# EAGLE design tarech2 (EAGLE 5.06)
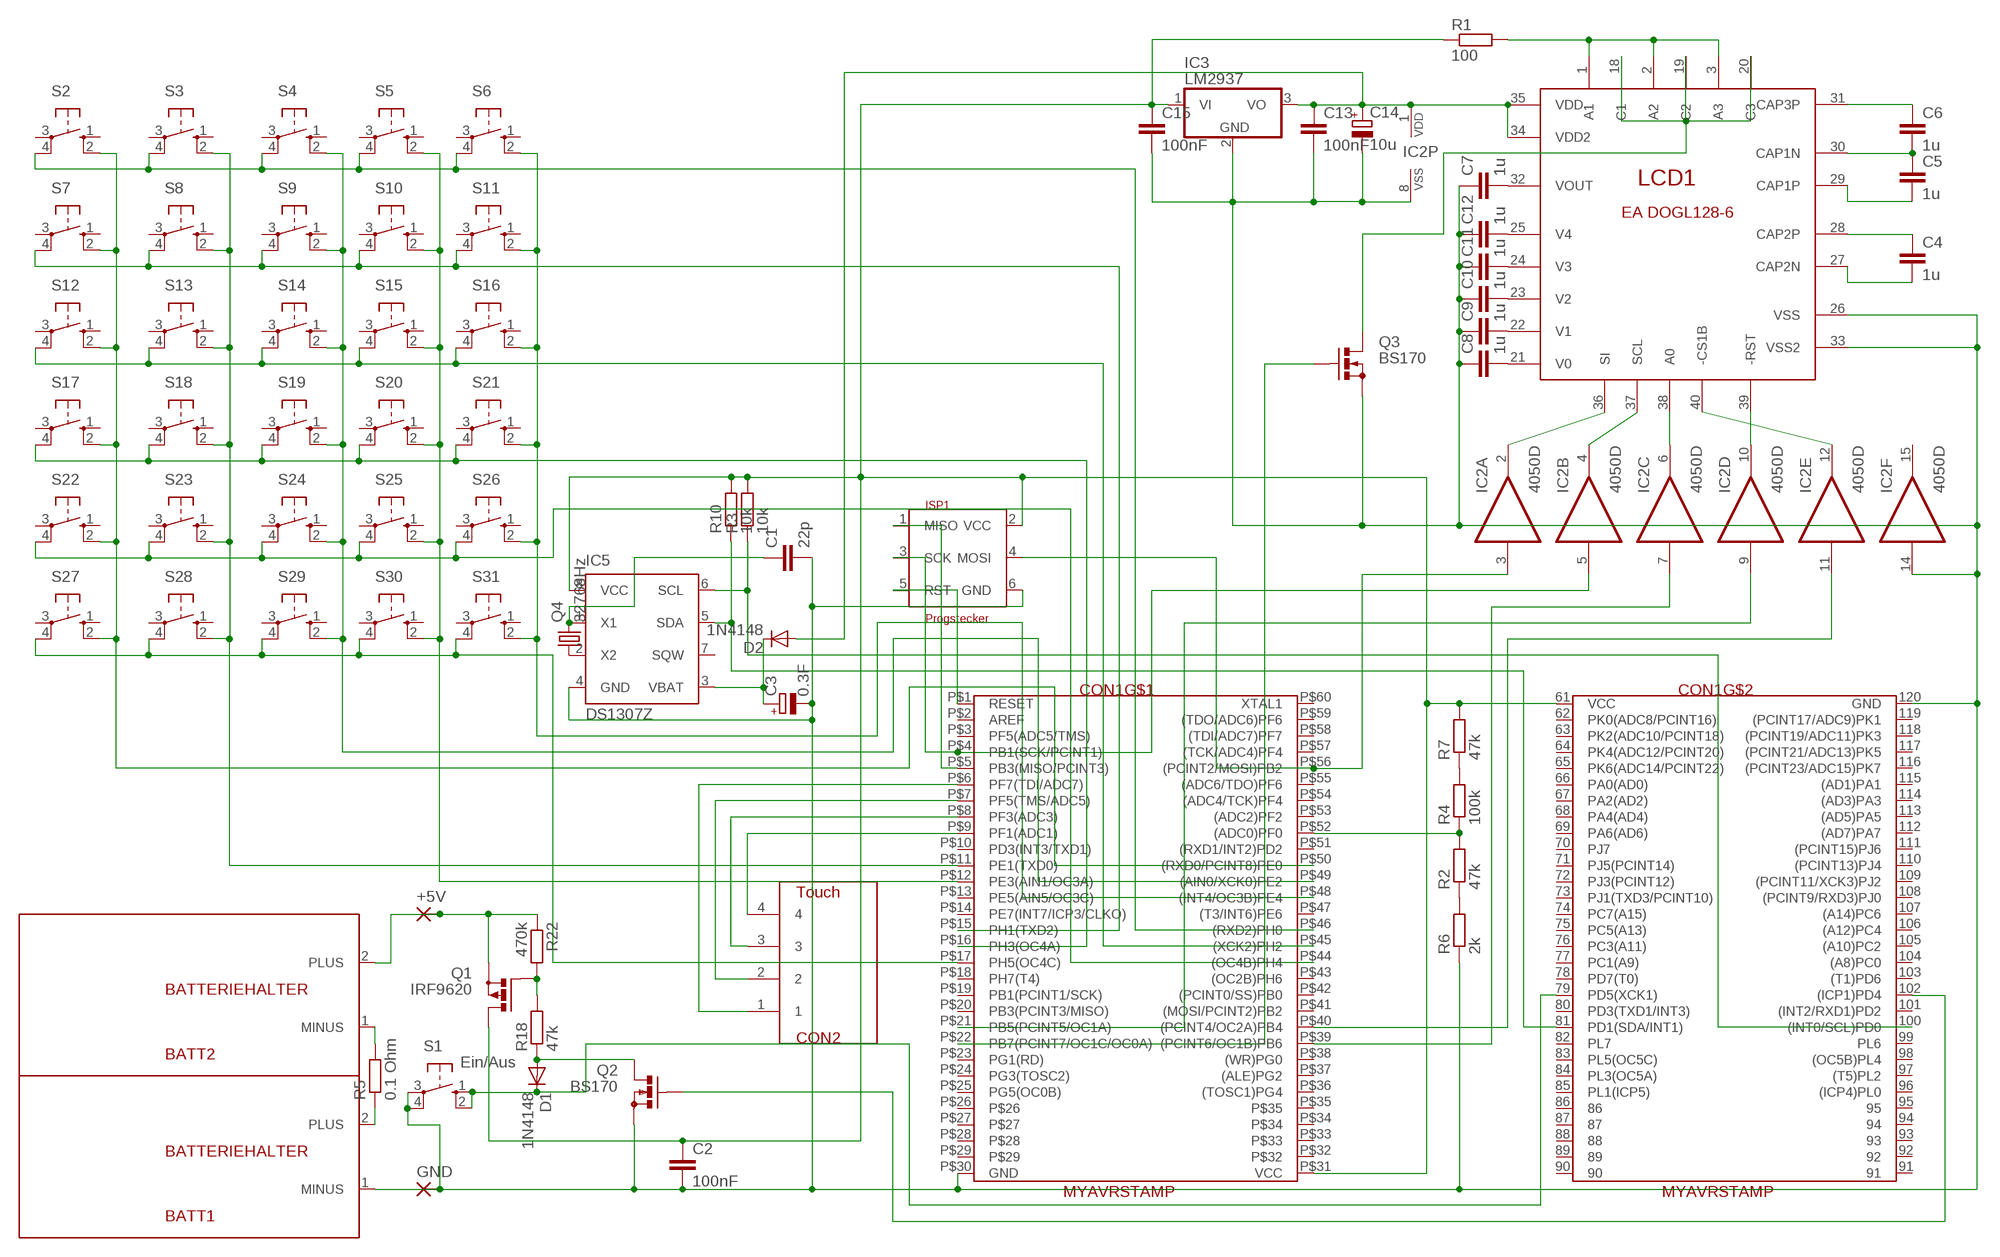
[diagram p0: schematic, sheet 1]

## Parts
+5V  WIREPAD2,54/1,0  [2,54/1,0]
BATT1  BATTERIEHALTER  [BATTERIEHALTER]
BATT2  BATTERIEHALTER  [BATTERIEHALTER]
C1  22p  C-EUC1206  [C1206]
C2  100nF  C-EU025-024X044  [C025-024X044]
C3  0.3F  CPOL-EUE3.5-8  [E3,5-8]
C4  1u  C-EUC0603K  [C0603K]
C5  1u  C-EUC0603K  [C0603K]
C6  1u  C-EUC0603K  [C0603K]
C7  1u  C-EUC0603K  [C0603K]
C8  1u  C-EUC0603K  [C0603K]
C9  1u  C-EUC0603K  [C0603K]
C10  1u  C-EUC0603K  [C0603K]
C11  1u  C-EUC0603K  [C0603K]
C12  1u  C-EUC0603K  [C0603K]
C13  100nF  C-EU025-024X044  [C025-024X044]
C14  10u  CPOL-EUE3.5-8  [E3,5-8]
C15  100nF  C-EU025-024X044  [C025-024X044]
CON1  MYAVRSTAMP  [MYAVRSTAMP]
CON2  Touch  FLEX4POL  [FLEX4POL]
D1  1N4148  [DO35-10]
D2  1N4148  [DO35-10]
GND  WIREPAD2,54/1,0  [2,54/1,0]
IC2  4050D  [SO16]
IC3  LM2937  7805T  [TO220H]
IC5  DS1307Z  [SOIC8]
ISP1  Progstecker  ISP6N  [ISP6]
LCD1  EADOGL128  [EADOGL128]
Q1  IRF9620  PMOSFET_PTO220BH  [TO220BH]
Q2  BS170  [SOT54E]
Q3  BS170  [SOT54E]
Q4  32768Hz  CRYTALTC26H  [TC26H]
R1  100  R-EU_M1406  [M1406]
R2  47k  R-EU_M1406  [M1406]
R3  10k  R-EU_M1406  [M1406]
R4  100k  R-EU_M1406  [M1406]
R5  0.1 Ohm  R-EU_0204/7  [0204/7]
R6  2k  R-EU_M1406  [M1406]
R7  47k  R-EU_M1406  [M1406]
R10  10k  R-EU_M1406  [M1406]
R18  47k  R-EU_M1406  [M1406]
R22  470k  R-EU_M1406  [M1406]
S1  Ein/Aus  10-XX  [B3F-10XX]
S2  10-XX  [B3F-10XX]
S3  10-XX  [B3F-10XX]
S4  10-XX  [B3F-10XX]
S5  10-XX  [B3F-10XX]
S6  10-XX  [B3F-10XX]
S7  10-XX  [B3F-10XX]
S8  10-XX  [B3F-10XX]
S9  10-XX  [B3F-10XX]
S10  10-XX  [B3F-10XX]
S11  10-XX  [B3F-10XX]
S12  10-XX  [B3F-10XX]
S13  10-XX  [B3F-10XX]
S14  10-XX  [B3F-10XX]
S15  10-XX  [B3F-10XX]
S16  10-XX  [B3F-10XX]
S17  10-XX  [B3F-10XX]
S18  10-XX  [B3F-10XX]
S19  10-XX  [B3F-10XX]
S20  10-XX  [B3F-10XX]
S21  10-XX  [B3F-10XX]
S22  10-XX  [B3F-10XX]
S23  10-XX  [B3F-10XX]
S24  10-XX  [B3F-10XX]
S25  10-XX  [B3F-10XX]
S26  10-XX  [B3F-10XX]
S27  10-XX  [B3F-10XX]
S28  10-XX  [B3F-10XX]
S29  10-XX  [B3F-10XX]
S30  10-XX  [B3F-10XX]
S31  10-XX  [B3F-10XX]

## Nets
GND [DICK]: BATT1.1(MINUS) C1.2 C2.2 C3.- C7.1 C8.1 C9.1 C10.1 C11.1 C12.1 C13.2 C14.- C15.2 CON1.120(GND) CON1.P$30(GND) GND.1(P) IC2.8(P:VSS) IC2.14(F:I) IC3.2(GND) IC5.4(GND) ISP1.6(GND) LCD1.26(VSS) LCD1.33(VSS2) Q2.S Q3.S R6.1 S1.3(P) S1.4(P1)
N$1: C4.1 LCD1.28(CAP2P)
N$2 [DICK]: +5V.1(P) BATT2.2(PLUS) Q1.S R22.1
N$3: CON1.P$56((PCINT2/MOSI)PB2) IC2.3(A:I) ISP1.4(MOSI)
N$4: C3.+ D2.C IC5.3(VBAT)
N$5 [DICK]: BATT1.2(PLUS) R5.1
N$6: C4.2 LCD1.27(CAP2N)
N$7: C1.1 IC5.1(X1) Q4.2
N$8: CON1.79(PD5(XCK1)) D1.C S1.1(S) S1.2(S1)
N$9: C5.1 C6.2 LCD1.30(CAP1N)
N$10: C5.2 LCD1.29(CAP1P)
N$11: IC5.2(X2) Q4.1
N$12: C6.1 LCD1.31(CAP3P)
N$13: C7.2 LCD1.32(VOUT)
N$14: C8.2 LCD1.21(V0)
N$15: C9.2 LCD1.22(V1)
N$16: C10.2 LCD1.23(V2)
N$17: LCD1.1(A1) LCD1.2(A2) LCD1.3(A3) R1.2
N$18: LCD1.18(C1) LCD1.19(C2) LCD1.20(C3) Q3.D
N$19: C11.2 LCD1.24(V3)
N$20: C12.2 LCD1.25(V4)
N$21: CON1.P$4(PB1(SCK/PCINT1)) IC2.5(B:I) ISP1.3(SCK)
N$22: IC2.2(A:O) LCD1.36(SI)
N$23: IC2.4(B:O) LCD1.37(SCL)
N$24: IC2.6(C:O) LCD1.38(A0)
N$25: IC2.10(D:O) LCD1.39(-RST)
N$26: IC2.12(E:O) LCD1.40(-CS1B)
N$27: Q1.G R18.2 R22.2
N$28: D1.A Q2.D R18.1
N$29: CON1.P$39((PCINT6/OC1B)PB6) IC2.7(C:I)
N$30: CON1.P$21(PB5(PCINT5/OC1A)) IC2.9(D:I)
N$31: CON1.P$40((PCINT4/OC2A)PB4) IC2.11(E:I)
N$32: CON1.81(PD1(SDA/INT1)) IC5.5(SDA) R10.1
N$33: CON1.100((INT0/SCL)PD0) IC5.6(SCL) R3.1
N$34: CON1.102((ICP1)PD4) Q2.G
N$35: CON1.P$22(PB7(PCINT7/OC1C/OC0A)) Q3.G
N$36: CON1.P$48((INT4/OC3B)PE4) S6.2(S1) S11.2(S1) S16.2(S1) S21.2(S1) S26.2(S1) S31.2(S1)
N$37: CON1.P$12(PE3(AIN1/OC3A)) S5.2(S1) S10.2(S1) S15.2(S1) S20.2(S1) S25.2(S1) S30.2(S1)
N$38: CON1.P$50((RXD0/PCINT8)PE0) S2.2(S1) S7.2(S1) S12.2(S1) S17.2(S1) S22.2(S1) S27.2(S1)
N$39: CON1.P$11(PE1(TXD0)) S3.2(S1) S8.2(S1) S13.2(S1) S18.2(S1) S23.2(S1) S28.2(S1)
N$40: CON1.P$5(PB3(MISO/PCINT3)) ISP1.1(MISO)
N$41: CON1.P$1(RESET) ISP1.5(RST)
N$42: CON1.P$52((ADC0)PF0) R2.2 R4.1
N$43: CON1.P$49((AIN0/XCK0)PE2) S4.2(S1) S9.2(S1) S14.2(S1) S19.2(S1) S24.2(S1) S29.2(S1)
N$44: CON1.P$6(PF7(TDI/ADC7)) CON2.1
N$45: CON1.P$7(PF5(TMS/ADC5)) CON2.2
N$46: CON1.P$8(PF3(ADC3)) CON2.3
N$47: CON1.P$46((RXD2)PH0) S2.4(P1) S3.4(P1) S4.4(P1) S5.4(P1) S6.4(P1)
N$48: CON1.P$15(PH1(TXD2)) S7.4(P1) S8.4(P1) S9.4(P1) S10.4(P1) S11.4(P1)
N$49: CON1.P$45((XCK2)PH2) S12.4(P1) S13.4(P1) S14.4(P1) S15.4(P1) S16.4(P1)
N$50: CON1.P$16(PH3(OC4A)) S17.4(P1) S18.4(P1) S19.4(P1) S20.4(P1) S21.4(P1)
N$51: CON1.P$44((OC4B)PH4) S22.4(P1) S23.4(P1) S24.4(P1) S25.4(P1) S26.4(P1)
N$52: CON1.P$17(PH5(OC4C)) S27.4(P1) S28.4(P1) S29.4(P1) S30.4(P1) S31.4(P1)
N$53: CON1.P$9(PF1(ADC1)) CON2.4
N$54 [DICK]: BATT2.1(MINUS) R5.2
N$55 [DICK]: R2.1 R6.2
N$56 [DICK]: R4.2 R7.1
VCC [DICK]: C2.1 C15.1 CON1.61(VCC) CON1.P$31(VCC) IC3.1(VI) IC5.8(VCC) ISP1.2(VCC) Q1.D R1.1 R3.2 R7.2 R10.2
VDD [DICK]: C13.1 C14.+ D2.A IC2.1(P:VDD) IC3.3(VO) LCD1.34(VDD2) LCD1.35(VDD)
Unconnected: CON1.62(PK0(ADC8/PCINT16)) CON1.63(PK2(ADC10/PCINT18)) CON1.64(PK4(ADC12/PCINT20)) CON1.65(PK6(ADC14/PCINT22)) CON1.66(PA0(AD0)) CON1.67(PA2(AD2)) CON1.68(PA4(AD4)) CON1.69(PA6(AD6)) CON1.70(PJ7) CON1.71(PJ5(PCINT14)) CON1.72(PJ3(PCINT12)) CON1.73(PJ1(TXD3/PCINT10)) CON1.74(PC7(A15)) CON1.75(PC5(A13)) CON1.76(PC3(A11)) CON1.77(PC1(A9)) CON1.78(PD7(T0)) CON1.80(PD3(TXD1/INT3)) CON1.82(PL7) CON1.83(PL5(OC5C)) CON1.84(PL3(OC5A)) CON1.85(PL1(ICP5)) CON1.86 CON1.87 CON1.88 CON1.89 CON1.90 CON1.91 CON1.92 CON1.93 CON1.94 CON1.95 CON1.96((ICP4)PL0) CON1.97((T5)PL2) CON1.98((OC5B)PL4) CON1.99(PL6) CON1.101((INT2/RXD1)PD2) CON1.103((T1)PD6) CON1.104((A8)PC0) CON1.105((A10)PC2) CON1.106((A12)PC4) CON1.107((A14)PC6) CON1.108((PCINT9/RXD3)PJ0) CON1.109((PCINT11/XCK3)PJ2) CON1.110((PCINT13)PJ4) CON1.111((PCINT15)PJ6) CON1.112((AD7)PA7) CON1.113((AD5)PA5) CON1.114((AD3)PA3) CON1.115((AD1)PA1) CON1.116((PCINT23/ADC15)PK7) CON1.117((PCINT21/ADC13)PK5) CON1.118((PCINT19/ADC11)PK3) CON1.119((PCINT17/ADC9)PK1) CON1.P$2(AREF) CON1.P$3(PF5(ADC5/TMS)) CON1.P$10(PD3(INT3/TXD1)) CON1.P$13(PE5(AIN5/OC3C)) CON1.P$14(PE7(INT7/ICP3/CLKO)) CON1.P$18(PH7(T4)) CON1.P$19(PB1(PCINT1/SCK)) CON1.P$20(PB3(PCINT3/MISO)) CON1.P$23(PG1(RD)) CON1.P$24(PG3(TOSC2)) CON1.P$25(PG5(OC0B)) CON1.P$26 CON1.P$27 CON1.P$28 CON1.P$29 CON1.P$32 CON1.P$33 CON1.P$34 CON1.P$35 CON1.P$36((TOSC1)PG4) CON1.P$37((ALE)PG2) CON1.P$38((WR)PG0) CON1.P$41((MOSI/PCINT2)PB2) CON1.P$42((PCINT0/SS)PB0) CON1.P$43((OC2B)PH6) CON1.P$47((T3/INT6)PE6) CON1.P$51((RXD1/INT2)PD2) CON1.P$53((ADC2)PF2) CON1.P$54((ADC4/TCK)PF4) CON1.P$55((ADC6/TDO)PF6) CON1.P$57((TCK/ADC4)PF4) CON1.P$58((TDI/ADC7)PF7) CON1.P$59((TDO/ADC6)PF6) CON1.P$60(XTAL1) IC2.15(F:O) IC5.7(SQW) S2.1(S) S2.3(P) S3.1(S) S3.3(P) S4.1(S) S4.3(P) S5.1(S) S5.3(P) S6.1(S) S6.3(P) S7.1(S) S7.3(P) S8.1(S) S8.3(P) S9.1(S) S9.3(P) S10.1(S) S10.3(P) S11.1(S) S11.3(P) S12.1(S) S12.3(P) S13.1(S) S13.3(P) S14.1(S) S14.3(P) S15.1(S) S15.3(P) S16.1(S) S16.3(P) S17.1(S) S17.3(P) S18.1(S) S18.3(P) S19.1(S) S19.3(P) S20.1(S) S20.3(P) S21.1(S) S21.3(P) S22.1(S) S22.3(P) S23.1(S) S23.3(P) S24.1(S) S24.3(P) S25.1(S) S25.3(P) S26.1(S) S26.3(P) S27.1(S) S27.3(P) S28.1(S) S28.3(P) S29.1(S) S29.3(P) S30.1(S) S30.3(P) S31.1(S) S31.3(P)

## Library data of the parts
+5V GND = wirepad:WIREPAD: Wire PAD connect wire on PCB
BATT1 BATT2 = 11_rolfp:BATTERIEHALTER: Halter fuer 2 AAA Batterien
C1 C2 C4-C13 C15 = rcl:C-EU: CAPACITOR, European symbol
C3 C14 = rcl:CPOL-EU: POLARIZED CAPACITOR, European symbol
CON1 = myStamp:MYAVRSTAMP: Anschluss fuer MyAvrStamp bestehend aus 2 Steckern
CON2 = stecker:FLEX4POL: 4-Poliger Stecker fuer Touchscreen
D1 D2 = diode:1N4148: DIODE
IC2 = 40xx:4050: Hex non-inverting BUFFER
IC3 = linear:78*: Positive VOLTAGE REGULATOR Source: http://cache.national.com/ds/LM/LM78L05.pdf http://www.fairchildsemi.com/ds/LM/LM7805.pdf
IC5 = ds1307_pcf8583:DS1307: I2C-Bus CLOCK/CALENDAR
ISP1 = stecker:ISP6: ISP-Stecker 6polig
LCD1 = ea-DOGL:EADOGL128
Q1 = transistor-power:PMOSFET_P: Power MOSFET P-Channel
Q2 Q3 = transistor-small-signal:BS170: N-CHANNEL MOS FET
Q4 = crystal:CRYTAL: CRYSTAL
R1-R7 R10 R18 R22 = rcl:R-EU_: RESISTOR, European symbol
S1-S31 = switch-omron:10-XX: OMRON SWITCH

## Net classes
1 DICK: width 0.635 mm

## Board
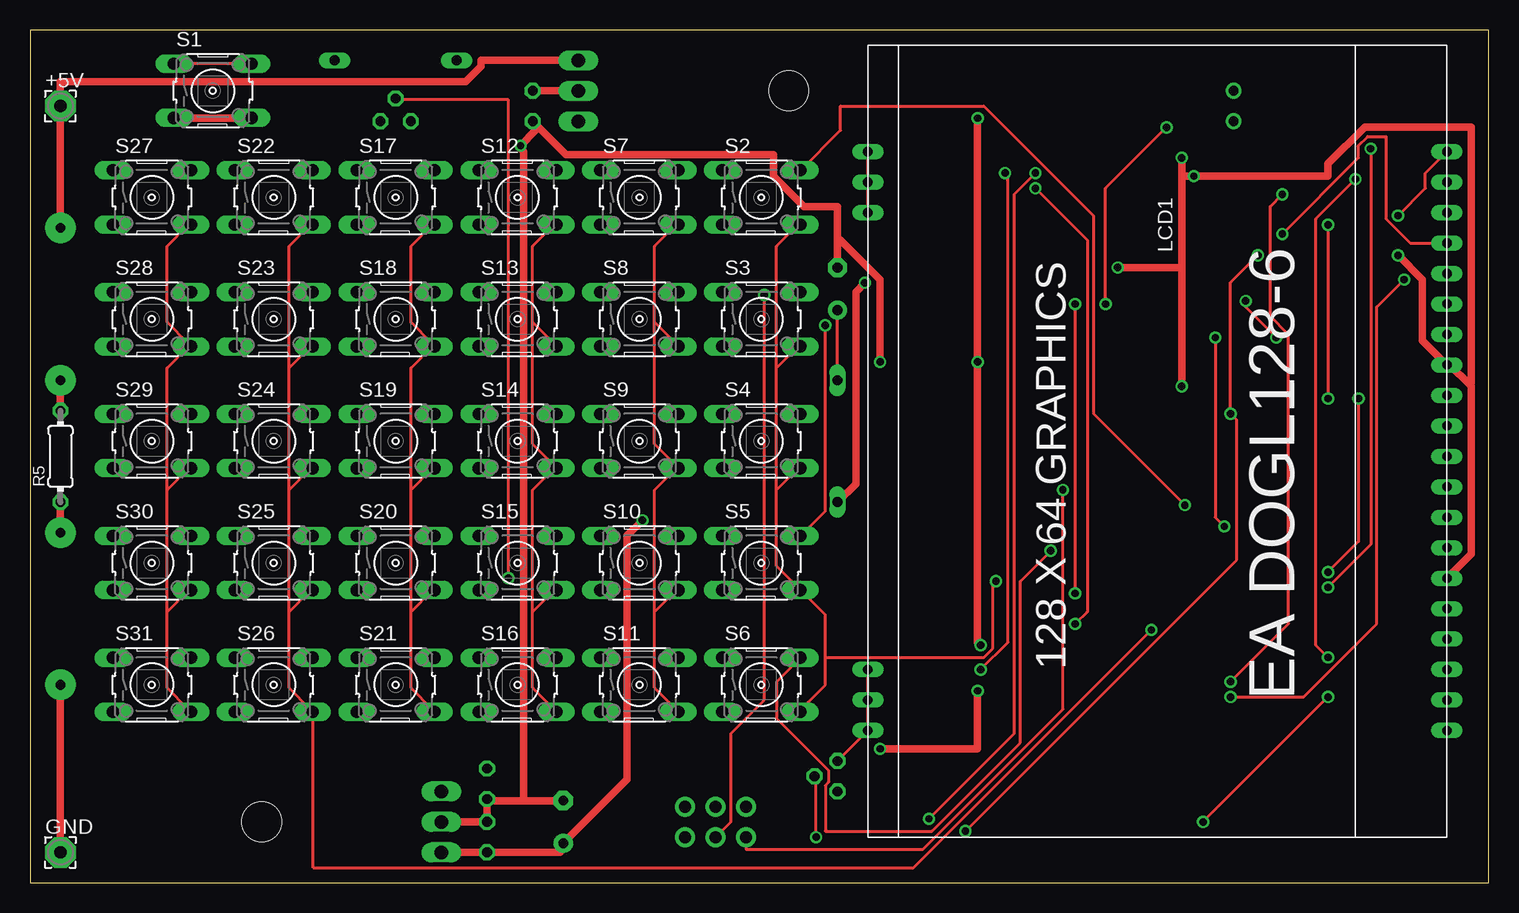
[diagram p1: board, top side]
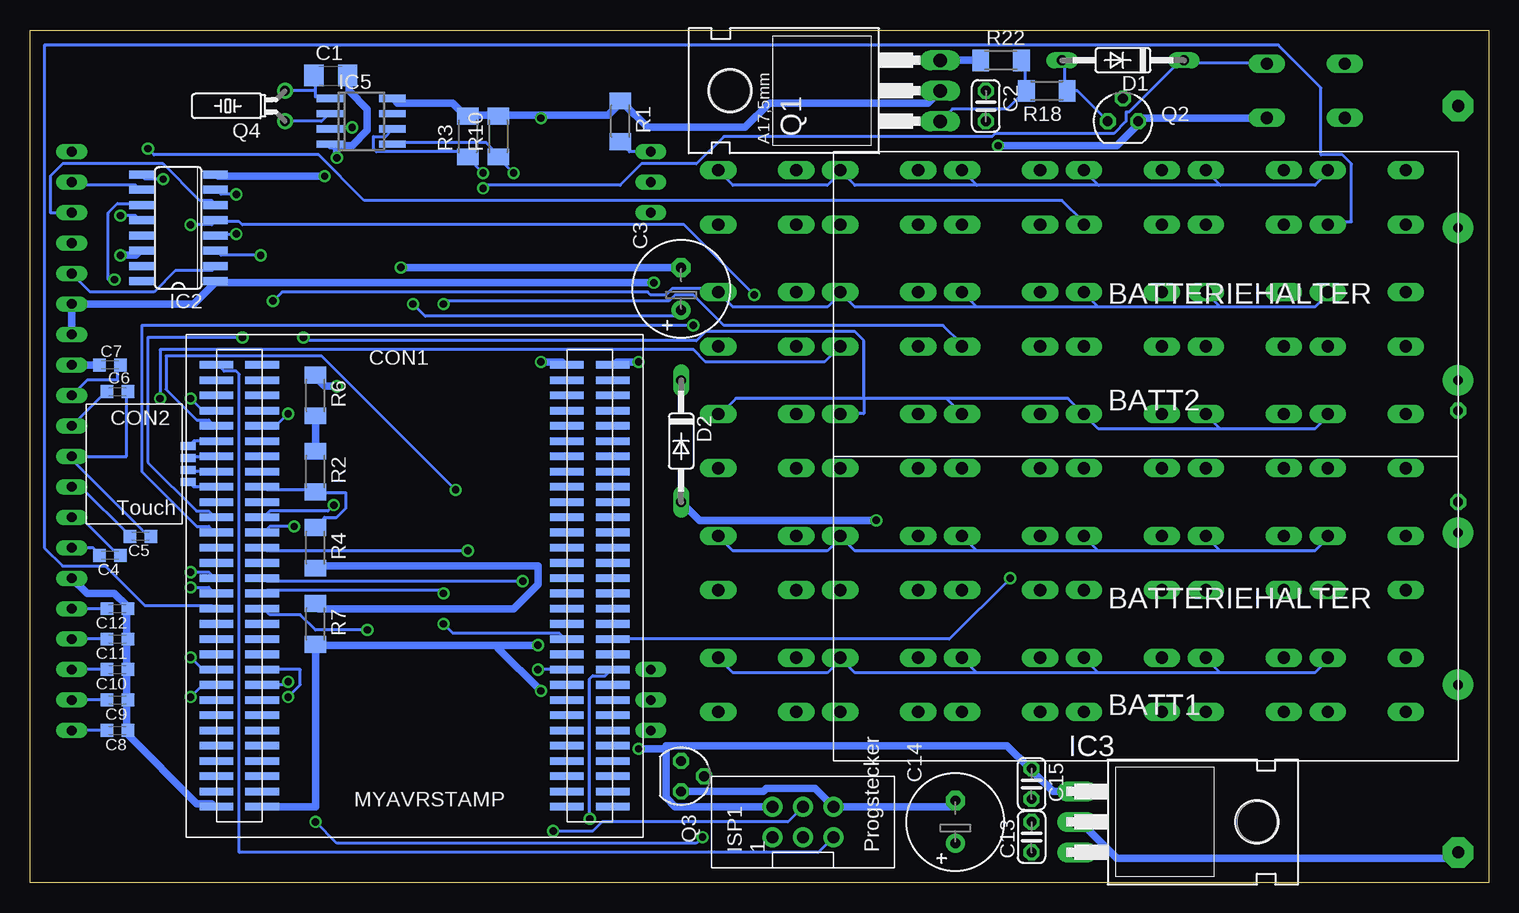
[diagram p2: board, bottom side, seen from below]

Size 121.59 x 71.11 mm. Coordinates in mm from the lower left corner, seen from the top.
Outline: 0,0 121.59,0 121.59,71.11 0,71.11 0,0
Copper layers (1*16): Top 0.035mm / dielectric 1.5mm / Bottom 0.035mm
Design rules "default": minimum track width 10mil, minimum drill 24mil, track to track 8mil, track to pad 8mil, pad to pad 8mil, via to via 8mil, smd to smd 8mil, copper to edge 40mil, drill to drill 8mil, minimum pad ring 10mil, minimum via ring 8mil, stop-mask expansion 4mil, vias tented up to drill 0mil, thermal gap 10mil

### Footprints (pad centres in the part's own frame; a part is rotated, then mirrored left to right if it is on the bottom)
2,54/1,0 = drill 1.016 pad 2.54 octagon: 1 0,0
BATTERIEHALTER = drill 0.8 pad 2.54 round: 1 26.67,-6.35; 2 26.67,6.35
C1206 = smd 1.6 x 1.8: 1 -1.4,0; 2 1.4,0
C025-024X044 = drill 0.813 octagon: 1 -1.27,0; 2 1.27,0
E3,5-8 = drill 0.813 pad 1.6 round: + -1.778,0 | drill 0.813 pad 1.6 octagon: - 1.778,0
C0603K = smd 1.05 x 1.08: 1 -0.875,0; 2 0.875,0
MYAVRSTAMP = smd 2.794 x 0.635: 61 12.7,17.78; 62 12.7,16.51; 63 12.7,15.24; 64 12.7,13.97; 65 12.7,12.7; 66 12.7,11.43; 67 12.7,10.16; 68 12.7,8.89; 69 12.7,7.62; 70 12.7,6.35; 71 12.7,5.08; 72 12.7,3.81; 73 12.7,2.54; 74 12.7,1.27; 75 12.7,0; 76 12.7,-1.27; 77 12.7,-2.54; 78 12.7,-3.81; 79 12.7,-5.08; 80 12.7,-6.35; 81 12.7,-7.62; 82 12.7,-8.89; 83 12.7,-10.16; 84 12.7,-11.43; 85 12.7,-12.7; 86 12.7,-13.97; 87 12.7,-15.24; 88 12.7,-16.51; 89 12.7,-17.78; 90 12.7,-19.05; 91 16.51,-19.05; 92 16.51,-17.78; 93 16.51,-16.51; 94 16.51,-15.24; 95 16.51,-13.97; 96 16.51,-12.7; 97 16.51,-11.43; 98 16.51,-10.16; 99 16.51,-8.89; 100 16.51,-7.62; 101 16.51,-6.35; 102 16.51,-5.08; 103 16.51,-3.81; 104 16.51,-2.54; 105 16.51,-1.27; 106 16.51,0; 107 16.51,1.27; 108 16.51,2.54; 109 16.51,3.81; 110 16.51,5.08; 111 16.51,6.35; 112 16.51,7.62; 113 16.51,8.89; 114 16.51,10.16; 115 16.51,11.43; 116 16.51,12.7; 117 16.51,13.97; 118 16.51,15.24; 119 16.51,16.51; 120 16.51,17.78; P$1 -16.51,17.78; P$2 -16.51,16.51; P$3 -16.51,15.24; P$4 -16.51,13.97; P$5 -16.51,12.7; P$6 -16.51,11.43; P$7 -16.51,10.16; P$8 -16.51,8.89; P$9 -16.51,7.62; P$10 -16.51,6.35; P$11 -16.51,5.08; P$12 -16.51,3.81; P$13 -16.51,2.54; P$14 -16.51,1.27; P$15 -16.51,0; P$16 -16.51,-1.27; P$17 -16.51,-2.54; P$18 -16.51,-3.81; P$19 -16.51,-5.08; P$20 -16.51,-6.35; P$21 -16.51,-7.62; P$22 -16.51,-8.89; P$23 -16.51,-10.16; P$24 -16.51,-11.43; P$25 -16.51,-12.7; P$26 -16.51,-13.97; P$27 -16.51,-15.24; P$28 -16.51,-16.51; P$29 -16.51,-17.78; P$30 -16.51,-19.05; P$31 -12.7,-19.05; P$32 -12.7,-17.78; P$33 -12.7,-16.51; P$34 -12.7,-15.24; P$35 -12.7,-13.97; P$36 -12.7,-12.7; P$37 -12.7,-11.43; P$38 -12.7,-10.16; P$39 -12.7,-8.89; P$40 -12.7,-7.62; P$41 -12.7,-6.35; P$42 -12.7,-5.08; P$43 -12.7,-3.81; P$44 -12.7,-2.54; P$45 -12.7,-1.27; P$46 -12.7,0; P$47 -12.7,1.27; P$48 -12.7,2.54; P$49 -12.7,3.81; P$50 -12.7,5.08; P$51 -12.7,6.35; P$52 -12.7,7.62; P$53 -12.7,8.89; P$54 -12.7,10.16; P$55 -12.7,11.43; P$56 -12.7,12.7; P$57 -12.7,13.97; P$58 -12.7,15.24; P$59 -12.7,16.51; P$60 -12.7,17.78
FLEX4POL = smd 1.27 x 0.635: 1 -4,-1.5; 2 -4,-0.5; 3 -4,0.5; 4 -4,1.5
DO35-10 = drill 0.813 long: A 5.08,0; C -5.08,0
SO16 = smd 0.66 x 2.032: 1 -4.445,-3.073; 2 -3.175,-3.073; 3 -1.905,-3.073; 4 -0.635,-3.073; 5 0.635,-3.073; 6 1.905,-3.073; 7 3.175,-3.073; 8 4.445,-3.073; 9 4.445,3.073; 10 3.175,3.073; 11 1.905,3.073; 12 0.635,3.073; 13 -0.635,3.073; 14 -1.905,3.073; 15 -3.175,3.073; 16 -4.445,3.073
TO220H = drill 1.118 long: 1 -2.54,-10.16; 2 0,-10.16; 3 2.54,-10.16 | hole 3.302: 0,4.826
SOIC8 = smd 0.6 x 2.2: 1 -1.905,-2.6; 2 -0.635,-2.6; 3 0.635,-2.6; 4 1.905,-2.6; 5 1.905,2.6; 6 0.635,2.6; 7 -0.635,2.6; 8 -1.905,2.6
ISP6 = drill 1 pad 1.676 round: 1 -1.27,2.54; 2 1.27,2.54; 3 -1.27,0; 4 1.27,0; 5 -1.27,-2.54; 6 1.27,-2.54
EADOGL128 = drill 0.8 long: 1 -25.4,-26.67; 2 -22.86,-26.67; 3 -20.32,-26.67; 18 17.78,-26.67; 19 20.32,-26.67; 20 22.86,-26.67; 21 22.86,21.59; 22 20.32,21.59; 23 17.78,21.59; 24 15.24,21.59; 25 12.7,21.59; 26 10.16,21.59; 27 7.62,21.59; 28 5.08,21.59; 29 2.54,21.59; 30 0,21.59; 31 -2.54,21.59; 32 -5.08,21.59; 33 -7.62,21.59; 34 -10.16,21.59; 35 -12.7,21.59; 36 -15.24,21.59; 37 -17.78,21.59; 38 -20.32,21.59; 39 -22.86,21.59; 40 -25.4,21.59
TO220BH = drill 1.118 long: D 0,-6.35; G -2.54,-6.35; S 2.54,-6.35 | hole 3.302: 0,11.176
SOT54E = drill 0.813 octagon: D -1.27,0; G 0,1.905; S 1.27,0
TC26H = drill 0.813 round: 1 -1.27,0; 2 1.27,0
M1406 = smd 1.4 x 1.8: 1 -1.7,0; 2 1.7,0
0204/7 = drill 0.813 octagon: 1 -3.81,0; 2 3.81,0
B3F-10XX = drill 1.016 long: 1 -3.251,2.261; 2 3.251,2.261; 3 -3.251,-2.261; 4 3.251,-2.261

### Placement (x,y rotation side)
+5V  2.54,64.77 0 top
BATT1  29.21,22.86 0 bottom
BATT2  29.21,48.26 0 bottom
C1  96.52,67.31 0 bottom
C2  41.91,64.77 270 bottom
C3  67.31,49.53 90 bottom
C4  114.94,27.3 180 bottom
C5  112.39,28.89 180 bottom
C6  114.3,40.96 0 bottom
C7  114.94,43.18 0 bottom
C8  114.3,12.7 180 bottom
C9  114.3,15.24 180 bottom
C10  114.3,17.78 180 bottom
C11  114.3,20.32 180 bottom
C12  114.3,22.86 180 bottom
C13  38.1,3.81 90 bottom
C14  44.45,5.08 90 bottom
C15  38.1,8.26 270 bottom
CON1  89.53,25.4 0 bottom
CON2  112.39,34.92 180 bottom
D1  30.48,68.58 180 bottom
D2  67.31,36.83 270 bottom
GND  2.54,2.54 0 top
IC2  109.22,54.61 90 bottom
IC3  24.13,5.08 270 bottom
IC5  93.98,63.5 270 bottom
ISP1  57.15,5.08 90 bottom
LCD1  96.52,35.56 270 top
Q1  52.07,66.04 90 bottom
Q2  30.48,63.5 0 bottom
Q3  67.31,8.89 270 bottom
Q4  100.33,64.77 90 bottom
R1  72.39,63.5 270 bottom
R2  97.79,34.29 270 bottom
R3  85.09,62.23 90 bottom
R4  97.79,27.94 270 bottom
R5  2.54,35.56 90 top
R6  97.79,40.64 270 bottom
R7  97.79,21.59 270 bottom
R10  82.55,62.23 90 bottom
R18  36.83,66.04 180 bottom
R22  40.64,68.58 0 bottom
S1  15.24,66.04 0 top
S2  60.96,57.15 0 top
S3  60.96,46.99 0 top
S4  60.96,36.83 0 top
S5  60.96,26.67 0 top
S6  60.96,16.51 0 top
S7  50.8,57.15 0 top
S8  50.8,46.99 0 top
S9  50.8,36.83 0 top
S10  50.8,26.67 0 top
S11  50.8,16.51 0 top
S12  40.64,57.15 0 top
S13  40.64,46.99 0 top
S14  40.64,36.83 0 top
S15  40.64,26.67 0 top
S16  40.64,16.51 0 top
S17  30.48,57.15 0 top
S18  30.48,46.99 0 top
S19  30.48,36.83 0 top
S20  30.48,26.67 0 top
S21  30.48,16.51 0 top
S22  20.32,57.15 0 top
S23  20.32,46.99 0 top
S24  20.32,36.83 0 top
S25  20.32,26.67 0 top
S26  20.32,16.51 0 top
S27  10.16,57.15 0 top
S28  10.16,46.99 0 top
S29  10.16,36.83 0 top
S30  10.16,26.67 0 top
S31  10.16,16.51 0 top

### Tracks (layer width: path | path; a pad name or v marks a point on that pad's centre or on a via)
GND  (via drill 0.61)
  Top 0.635: 96.01,58.93 v96.01,60.45 | 96.01,51.31 96.01,58.93 | 96.01,51.31 v96.01,41.4 | 96.01,58.93 v97.03,58.93 108.2,58.93 108.2,59.94 111.25,62.99 120.14,62.99 120.14,41.66 120.02,41.53 | v114.05,52.32 116.08,50.29 116.08,45.21 LCD1.33 118.36,43.18 120.02,41.53 | 120.02,41.53 120.14,41.4 120.14,27.43 LCD1.26 | S1.3 12.19,63.75 18.29,63.75 S1.4 | 67.31,53.59 C3.- | 67.31,53.59 67.31,56.39 64.52,56.39 61.98,58.93 61.98,60.71 44.7,60.71 C2.2 42.16,62.99 42.16,62.74 v40.89,61.47 40.89,61.21 41.15,60.96 41.15,6.86 | v70.87,43.43 70.87,50.29 67.56,53.59 67.31,53.59 | GND.1 BATT1.1 | 41.15,6.86 38.35,6.86 C15.2 C13.2 IC3.2 | 41.15,6.86 C14.- | v90.68,51.31 96.01,51.31
  Bottom 0.635: v96.01,41.4 97.03,41.4 97.79,42.16 R6.1 | v96.01,60.45 96.01,61.47 96.52,61.47 IC5.4 95.76,61.47 94.74,61.47 93.47,62.74 93.47,64.52 95,66.04 95,67.31 C1.2 | v97.03,58.93 105.92,58.93 IC2.8 | LCD1.33 C7.1 | v114.05,52.32 112.78,52.32 112.52,52.58 IC2.14 | LCD1.26 116.84,24.13 114.55,24.13 113.54,23.11 C12.1 113.54,22.86 113.54,20.57 C11.1 113.54,20.32 113.54,18.03 C10.1 113.54,17.78 113.54,15.49 C9.1 113.54,15.24 113.54,12.7 C8.1 113.54,12.45 107.7,6.6 106.43,6.6 106.17,6.35 CON1.P$30 | S1.4 18.54,63.75 28.96,63.75 Q2.S 29.21,63.25 30.99,61.47 v40.89,61.47 | v70.87,43.43 72.64,43.43 72.9,43.18 CON1.120 | Q3.S 60.45,7.62 60.2,7.87 56.13,7.87 ISP1.6 44.96,6.35 C14.- | GND.1 3.05,2.03 30.99,2.03 34.04,5.08 IC3.2 | C3.- v90.68,51.31
N$1
  Bottom 0.254: LCD1.28 117.35,30.48 114.3,27.43 C4.1
N$2
  Top 0.635: Q1.S 37.59,68.58 37.59,68.07 36.32,66.8 2.54,66.8 +5V.1 BATT2.2
  Bottom 0.635: Q1.S R22.1
N$3  (via drill 0.61)
  Top 0.254: v102.36,52.32 100.08,50.04 v100.08,39.12 100.58,38.61 100.58,26.92 v77.98,4.32
  Bottom 0.254: v102.36,52.32 105.66,52.32 105.92,52.58 IC2.3 | v100.08,39.12 101.09,38.1 CON1.P$56 | ISP1.4 58.42,5.08 73.91,5.08 74.68,4.32 v77.98,4.32
N$4  (via drill 0.61)
  Top 0.254: v94.74,62.99 89.66,57.91 v89.66,48.26 | D2.C C3.+
  Bottom 0.254: v94.74,62.99 96.52,62.99 IC5.3 | v89.66,48.26 88.65,47.24 67.82,47.24 C3.+
N$5
  Top 0.635: BATT1.2 R5.1
N$6
  Bottom 0.254: LCD1.27 116.33,27.94 115.82,27.43 C4.2
N$7
  Bottom 0.254: 97.79,66.04 97.79,65.53 96.77,65.53 IC5.1 | 97.79,66.04 97.79,67.31 C1.1 | 97.79,66.04 Q4.2
N$8  (via drill 0.61)
  Top 0.254: v87.12,21.59 88.14,22.61 88.14,53.59 v83.82,57.91 | S1.1 12.19,68.33 18.29,68.33 S1.2
  Bottom 0.254: S1.2 18.54,68.33 25.15,68.33 D1.C 25.65,68.58 29.97,64.26 30.23,64.26 30.23,63.5 31.24,62.48 41.15,62.48 41.4,62.23 63.75,62.23 66.04,59.94 70.61,59.94 72.39,58.17 83.57,58.17 v83.82,57.91 | v87.12,21.59 86.36,20.83 77.47,20.83 76.96,20.32 CON1.79
N$9
  Bottom 0.254: C5.1 111.76,28.96 118.11,35.31 LCD1.30 113.54,35.56 113.54,40.89 C6.2
N$10
  Bottom 0.254: LCD1.29 117.35,33.02 113.28,28.96 C5.2
N$11
  Bottom 0.254: Q4.1 97.28,63.5 96.77,64.01 IC5.2
N$12
  Bottom 0.254: LCD1.31 115.32,40.89 C6.1
N$13
  Bottom 0.254: LCD1.32 116.84,41.91 114.3,41.91 114.3,43.18 C7.2
N$14
  Bottom 0.254: C8.2 LCD1.21
N$15
  Bottom 0.254: C9.2 LCD1.22
N$16
  Bottom 0.254: C10.2 LCD1.23
N$17
  Top 0.254: LCD1.3 LCD1.2 LCD1.1
  Bottom 0.254: LCD1.1 71.63,60.96 72.39,61.72 R1.2
N$18
  Top 0.254: LCD1.18 LCD1.19 LCD1.20 Q3.D
N$19
  Bottom 0.254: C11.2 LCD1.24
N$20
  Bottom 0.254: C12.2 LCD1.25
N$21  (via drill 0.61)
  Top 0.254: v108.2,54.86 v108.2,40.39 | ISP1.3 58.42,5.08 58.42,12.45 61.21,15.24 v61.21,49.02
  Bottom 0.254: v108.2,54.86 106.43,54.86 106.17,55.12 IC2.5 105.92,55.12 104.14,55.12 103.89,54.86 67.06,54.86 v61.21,49.02 | v108.2,40.39 107.19,39.37 CON1.P$4
N$22
  Bottom 0.254: LCD1.36 116.59,49.28 111.25,49.28 109.47,51.05 106.43,51.05 106.17,51.31 IC2.2
N$23  (via drill 0.61)
  Top 0.254: v104.39,54.1 110.74,60.45 110.74,61.47 111.51,62.23 113.03,62.23 113.03,55.37 115.06,53.34 LCD1.37
  Bottom 0.254: v104.39,54.1 105.92,54.1 IC2.4
N$24
  Bottom 0.254: LCD1.38 119.89,55.88 119.89,58.93 118.87,59.94 110.49,59.94 107.44,56.9 106.43,56.9 106.17,56.64 IC2.6
N$25
  Bottom 0.254: LCD1.39 117.86,58.17 112.78,58.17 112.52,57.91 IC2.10
N$26  (via drill 0.61)
  Top 0.254: v114.05,55.63 116.33,57.91 116.33,59.18 LCD1.40
  Bottom 0.254: v114.05,55.63 112.78,55.63 112.52,55.37 IC2.12
N$27
  Bottom 0.254: 38.61,66.04 38.61,68.58 R22.2 | 38.61,66.04 40.13,64.52 44.7,64.52 Q1.G | 38.61,66.04 R18.2
N$28
  Bottom 0.254: D1.A 35.31,68.58 35.31,66.04 R18.1 34.29,66.04 Q2.D
N$29  (via drill 0.61)
  Top 0.254: v104.39,57.4 103.38,56.39 103.38,47.24 104.9,45.72 104.9,21.59 v100.08,16.76
  Bottom 0.254: v104.39,57.4 105.66,57.4 105.92,57.66 IC2.7 | v100.08,16.76 100.33,16.51 CON1.P$39
N$30  (via drill 0.61)
  Top 0.254: v110.49,58.67 107.19,55.37 107.19,19.81 v108.2,18.8
  Bottom 0.254: v110.49,58.67 112.01,58.67 112.27,58.93 IC2.9 | v108.2,18.8 107.19,17.78 CON1.P$21
N$31  (via drill 0.61)
  Top 0.254: v114.55,50.29 112.27,48.01 112.27,21.59 106.17,15.49 v100.08,15.49
  Bottom 0.254: v114.55,50.29 115.06,50.29 115.06,55.88 114.3,56.64 112.52,56.64 IC2.11 | v100.08,15.49 99.06,16.51 99.06,17.78 CON1.P$40
N$32  (via drill 0.61)
  Top 0.254: v79.25,17.78 81.53,20.07 81.53,58.93 v81.28,59.18
  Bottom 0.254: IC5.5 91.19,61.72 83.57,61.72 82.55,60.71 R10.1 82.55,60.45 v81.28,59.18 | CON1.81 v79.25,17.78
N$33  (via drill 0.61)
  Top 0.254: v74.93,5.33 82.04,12.45 82.04,57.4 v83.82,59.18
  Bottom 0.254: IC5.6 91.44,62.74 91.95,62.23 92.96,62.23 92.96,61.21 92.71,60.96 85.34,60.96 85.09,60.71 R3.1 85.09,60.45 v83.82,59.18 | v74.93,5.33 74.93,17.02 74.68,17.27 73.66,17.27 73.15,17.78 CON1.100
N$34  (via drill 0.61)
  Top 0.254: v39.88,25.4 39.88,65.28 30.48,65.28 Q2.G
  Bottom 0.254: v39.88,25.4 44.96,20.32 CON1.102
N$35  (via drill 0.61)
  Top 0.254: v65.53,3.81 65.53,8.89 Q3.G | v97.79,5.08 v108.2,15.49
  Bottom 0.254: v65.53,3.81 66.04,3.3 96.01,3.3 v97.79,5.08 | v108.2,15.49 107.19,16.51 CON1.P$22
N$36  (via drill 0.61)
  Top 0.254: v85.09,27.69 82.55,25.15 82.55,11.68 75.18,4.32 66.29,4.32 66.29,8.13 66.55,8.38 66.55,9.4 62.23,13.72 62.23,16.76 64.01,18.54 S6.2
  Bottom 0.254: 22.35,17.53 14.48,17.53 13.46,18.54 S31.2 | 22.35,17.53 23.37,18.54 S26.2 | 32.51,17.53 33.53,18.54 S21.2 | 22.35,17.53 32.51,17.53 | 42.67,17.53 43.69,18.54 S16.2 | 32.51,17.53 42.67,17.53 | 42.67,17.53 52.83,17.53 53.85,18.54 S11.2 54.1,18.54 55.12,17.53 62.99,17.53 64.01,18.54 S6.2 | v85.09,27.69 101.85,27.69 102.11,27.94 CON1.P$48
N$37  (via drill 0.61)
  Top 0.254: v66.29,46.48 66.29,30.99 64.26,28.96 S5.2
  Bottom 0.254: 22.35,27.69 14.48,27.69 13.46,28.7 S30.2 | 22.35,27.69 23.37,28.7 S25.2 | 32.51,27.69 33.53,28.7 S20.2 | 22.35,27.69 32.51,27.69 | 42.67,27.69 43.69,28.7 S15.2 | 32.51,27.69 42.67,27.69 | 42.67,27.69 52.83,27.69 53.85,28.7 S10.2 54.1,28.7 55.12,27.69 62.99,27.69 64.01,28.7 S5.2 | v66.29,46.48 112.27,46.48 112.27,34.29 107.7,29.72 106.68,29.72 106.17,29.21 CON1.P$12
N$38  (via drill 0.61)
  Top 0.254: v96.27,31.5 88.65,39.12 88.65,55.63 79.5,64.77 67.56,64.77 67.56,62.74 64.26,59.44 S2.2
  Bottom 0.254: 22.35,58.17 14.48,58.17 13.46,59.18 S27.2 | 22.35,58.17 23.37,59.18 S22.2 | 32.51,58.17 33.53,59.18 S17.2 | 22.35,58.17 32.51,58.17 | 42.67,58.17 43.69,59.18 S12.2 | 32.51,58.17 42.67,58.17 | 42.67,58.17 52.83,58.17 53.85,59.18 S7.2 54.1,59.18 55.12,58.17 62.99,58.17 64.01,59.18 S2.2 | v96.27,31.5 96.77,30.99 101.6,30.99 102.11,30.48 CON1.P$50
N$39  (via drill 0.61)
  Top 0.254: v103.89,45.47 101.35,48.01 v101.35,48.51
  Bottom 0.254: 22.35,48.01 14.48,48.01 13.46,49.02 S28.2 | 22.35,48.01 23.37,49.02 S23.2 | 32.51,48.01 33.53,49.02 S18.2 | 22.35,48.01 32.51,48.01 | 42.67,48.01 43.69,49.02 S13.2 | 32.51,48.01 42.67,48.01 | 42.67,48.01 52.83,48.01 53.85,49.02 S8.2 54.1,49.02 55.12,48.01 62.99,48.01 64.01,49.02 S3.2 64.26,49.28 64.52,49.53 68.07,49.53 68.58,49.02 69.85,49.02 70.1,49.28 100.58,49.28 v101.35,48.51 | v103.89,45.47 111.76,45.47 111.76,35.05 107.7,30.99 106.68,30.99 106.17,30.48 CON1.P$11
N$40  (via drill 0.61)
  Top 0.254: v86.11,32.77 86.11,14.48 74.42,2.79 59.69,2.79 ISP1.1
  Bottom 0.254: v86.11,32.77 97.28,43.94 110.24,43.94 110.24,41.15 107.7,38.61 106.68,38.61 106.17,38.1 CON1.P$5
N$41
  Bottom 0.254: ISP1.5 55.88,2.54 104.14,2.54 104.14,42.42 104.39,42.67 105.41,42.67 105.92,43.18 CON1.P$1
N$42
  Bottom 0.254: R4.1 97.79,29.72 97.03,30.48 96.01,30.48 95.25,31.24 95.25,32.51 97.79,32.51 R2.2 97.79,32.77 101.85,32.77 102.11,33.02 CON1.P$52
N$43  (via drill 0.61)
  Top 0.254: v99.57,29.72 98.81,30.48 v98.81,45.47
  Bottom 0.254: 22.35,37.85 14.48,37.85 13.46,38.86 S29.2 | 22.35,37.85 23.37,38.86 S24.2 | 22.35,37.85 32.51,37.85 33.53,38.86 S19.2 33.78,39.12 35.05,40.39 45.21,40.39 | v99.57,29.72 101.6,29.72 102.11,29.21 CON1.P$49 | v98.81,45.47 98.55,45.21 66.04,45.21 65.28,45.97 52.83,45.97 52.07,45.21 52.07,40.39 | 52.07,40.39 52.07,39.12 53.85,39.12 S9.2 | 45.21,40.39 43.94,39.12 S14.2 | 45.21,40.39 52.07,40.39 | 52.07,40.39 62.74,40.39 64.01,39.12 S4.2
N$44
  Bottom 0.254: CON2.1 108.2,36.58 107.95,36.83 CON1.P$6
N$45
  Bottom 0.254: CON2.2 108.2,35.56 CON1.P$7
N$46
  Bottom 0.254: CON2.3 108.2,34.29 CON1.P$8
N$47  (via drill 0.61)
  Top 0.254: v80.52,25.15 80.26,24.89 80.26,19.56 79.5,18.8 66.29,18.8 | 66.29,18.8 66.29,16.51 64.26,14.48 S6.4 | 66.29,18.8 66.29,22.35 64.26,24.38 S5.4 64.01,24.64 62.23,26.42 62.23,32.77 | 62.23,32.77 64.01,34.54 S4.4 | 62.23,42.93 64.01,44.7 S3.4 | 62.23,32.77 62.23,42.93 | 62.23,42.93 62.23,53.09 64.01,54.86 S2.4
  Bottom 0.254: v80.52,25.15 101.85,25.15 102.11,25.4 CON1.P$46
N$48  (via drill 0.61)
  Top 0.254: 52.07,22.61 52.07,16.26 53.85,14.48 S11.4 | 52.07,22.61 53.85,24.38 S10.4 | 52.07,22.61 52.07,32.77 53.85,34.54 S9.4 53.85,34.8 52.07,36.58 52.07,46.74 | v108.2,25.91 110.74,28.45 v110.74,40.39 | 52.07,46.74 52.07,53.09 53.85,54.86 S7.4 | 52.07,46.74 53.85,44.96 S8.4
  Bottom 0.254: v108.2,25.91 106.68,25.91 106.17,25.4 CON1.P$15 | v110.74,40.39 110.74,44.45 66.29,44.45 65.28,43.43 55.37,43.43 54.1,44.7 S8.4
N$49  (via drill 0.61)
  Top 0.254: 41.91,22.61 41.91,16.26 43.69,14.48 S16.4 | 41.91,22.61 43.69,24.38 S15.4 | 41.91,22.61 41.91,32.77 43.69,34.54 S14.4 43.69,34.8 41.91,36.58 41.91,46.74 | v87.12,48.26 v87.12,24.13 | 41.91,46.74 41.91,53.09 43.69,54.86 S12.4 | 41.91,46.74 43.69,44.96 S13.4
  Bottom 0.254: v87.12,24.13 87.38,24.38 101.85,24.38 102.11,24.13 CON1.P$45 | v87.12,48.26 86.87,48.51 68.33,48.51 67.82,49.02 66.29,49.02 63.75,46.48 45.47,46.48 43.94,44.96 S13.4
N$50  (via drill 0.61)
  Top 0.254: 31.75,22.61 31.75,16.26 33.53,14.48 S21.4 | 31.75,22.61 33.53,24.38 S20.4 | 31.75,32.77 33.53,34.54 S19.4 | 31.75,22.61 31.75,32.77 | 31.75,32.77 31.75,42.93 33.53,44.7 S18.4 33.53,44.96 31.75,46.74 31.75,53.09 33.53,54.86 S17.4 | v108.2,24.64 111.76,28.19 v111.76,61.21
  Bottom 0.254: v108.2,24.64 106.68,24.64 106.17,24.13 CON1.P$16 | v111.76,61.21 111.25,60.71 97.54,60.71 93.73,56.9 35.56,56.9 33.78,55.12 S17.4
N$51  (via drill 0.61)
  Top 0.254: v93.47,21.08 73.66,1.27 23.62,1.27 23.62,14.22 S26.4 23.37,14.48 21.59,16.26 21.59,22.61 | 21.59,22.61 23.37,24.38 S25.4 | 21.59,32.77 23.37,34.54 S24.4 | 21.59,22.61 21.59,32.77 | 21.59,42.93 23.37,44.7 S23.4 | 21.59,32.77 21.59,42.93 | 21.59,42.93 21.59,53.09 23.37,54.86 S22.4
  Bottom 0.254: v93.47,21.08 97.79,21.08 99.06,22.35 101.6,22.35 102.11,22.86 CON1.P$44
N$52
  Top 0.254: 11.43,22.61 11.43,16.26 13.21,14.48 S31.4 | 11.43,22.61 13.21,24.38 S30.4 | 11.43,32.77 13.21,34.54 S29.4 | 11.43,22.61 11.43,32.77 | 11.43,32.77 11.43,42.93 13.21,44.7 S28.4 13.21,44.96 11.43,46.74 11.43,53.09 13.21,54.86 S27.4
  Bottom 0.254: CON1.P$17 106.17,22.86 106.43,23.11 112.01,23.11 115.32,26.42 118.87,26.42 120.4,27.94 120.4,69.85 17.53,69.85 13.97,66.29 13.97,60.71 12.19,60.71 11.43,59.94 11.43,55.12 13.21,55.12 S27.4
N$53
  Bottom 0.254: CON2.4 108.2,33.27 107.95,33.02 CON1.P$9
N$54
  Top 0.635: R5.2 BATT2.1
N$55
  Bottom 0.635: R2.1 R6.2
N$56
  Bottom 0.635: R7.1 97.79,23.11 97.54,22.86 81.28,22.86 79.25,24.89 79.25,26.42 97.79,26.42 R4.2
VCC  (via drill 0.61)
  Top 0.635: Q1.D C2.1 | v78.99,63.75 v78.99,43.43 78.99,20.07 v79.25,19.81 | v70.87,11.18 78.99,11.18 v78.99,16
  Bottom 0.635: IC3.1 36.32,7.62 38.1,9.4 C15.1 38.35,9.65 40.13,11.43 68.58,11.43 68.58,11.18 | ISP1.2 67.82,6.35 68.58,7.11 68.58,11.18 | CON1.P$31 97.79,6.35 R7.2 97.54,19.81 82.55,19.81 | 78.99,64.01 82.3,64.01 R10.2 82.55,64.01 85.09,64.01 R3.2 85.34,64.01 86.36,65.02 90.93,65.02 91.19,65.28 IC5.8 | 78.99,64.01 73.41,64.01 72.39,65.02 R1.1 72.14,65.02 70.1,62.99 61.98,62.99 59.94,65.02 46.74,65.02 Q1.D | v78.99,43.43 77.22,43.43 76.96,43.18 CON1.61 | v78.99,63.75 78.99,64.01 | 82.55,19.81 v79.25,19.81 | v78.99,16 82.55,19.56 82.55,19.81 | 68.58,11.18 v70.87,11.18
VDD  (via drill 0.61)
  Top 0.635: IC3.3 C13.1 44.2,2.54 44.2,3.3 C14.+ 49.78,8.64 49.78,28.96 v51.05,30.23 | v69.6,50.04 68.83,49.28 68.83,33.27 D2.A
  Bottom 0.635: LCD1.34 LCD1.35 107.95,48.26 106.17,50.04 IC2.1 105.92,50.04 v69.6,50.04 | D2.A 65.79,30.23 v51.05,30.23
